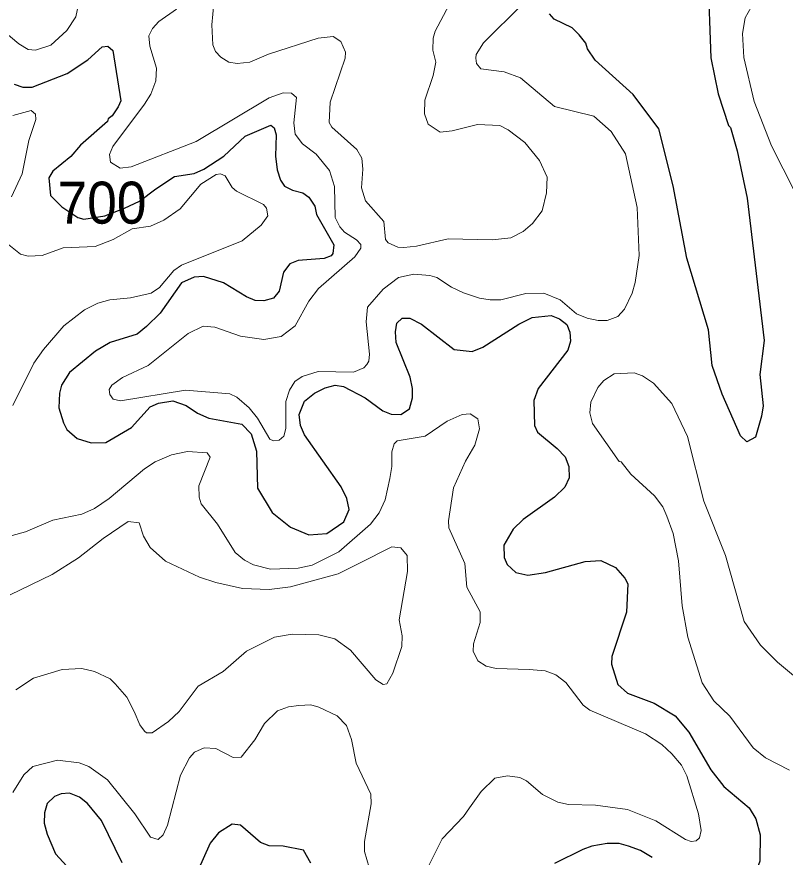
# Model space of a CAD drawing. Extents: x 294.2 to 320.3, y 7482.7 to 7510.7.
# Drawn here: x 307.613 to 309.078, y 7484.274 to 7485.877 of the extents above; entities that cross this region are included whole.
import ezdxf
from ezdxf.enums import TextEntityAlignment as Align

# ---------------------------------------------------------------- set-up
doc = ezdxf.new("R2010")
doc.units = 0
doc.header["$LTSCALE"] = 0.032
doc.layers.add('1', color=7, linetype='Continuous', lineweight=25)
doc.layers.add('2', color=7, linetype='Continuous', lineweight=13)
doc.layers.add('61', color=7, linetype='Continuous')

msp = doc.modelspace()

# ---------------------------------------------------------------- linework, layer by layer
at = {"layer": '1'}
for points in [[(308.9832, 7486.0825), (308.9632, 7486.0636), (308.9382, 7486.019), (308.9305, 7485.9565), (308.9358, 7485.7983), (308.9497, 7485.7295), (308.9699, 7485.6695)], [(308.9699, 7485.6695), (308.9737, 7485.6657), (308.9864, 7485.621), (309.005, 7485.531), (309.0376, 7485.259), (309.0297, 7485.1946), (309.0358, 7485.1349), (309.0325, 7485.115), (309.0209, 7485.0747), (309.0048, 7485.0661), (308.9926, 7485.0774), (308.9578, 7485.1569), (308.9386, 7485.2118), (308.9315, 7485.2798), (308.8901, 7485.4161), (308.864, 7485.554), (308.8367, 7485.6631), (308.7878, 7485.7287), (308.7157, 7485.7939), (308.7007, 7485.8159), (308.6974, 7485.8267), (308.6847, 7485.8423), (308.6719, 7485.8557), (308.6375, 7485.8724), (308.6281, 7485.8821)], [(307.6074, 7485.7481), (307.6241, 7485.7427), (307.6419, 7485.7427), (307.7084, 7485.7684), (307.7478, 7485.7948), (307.7756, 7485.8196), (307.7861, 7485.8207), (307.7956, 7485.8126), (307.8111, 7485.7162), (307.806, 7485.7047), (307.7945, 7485.688), (307.7868, 7485.6823), (307.7856, 7485.6772), (307.734, 7485.6318), (307.7159, 7485.6101), (307.6814, 7485.5821), (307.6737, 7485.5697), (307.677, 7485.5358), (307.6984, 7485.5142), (307.729, 7485.4938), (307.7401, 7485.4906), (307.7806, 7485.497), (307.8181, 7485.5117), (307.8464, 7485.5251), (307.8775, 7485.5483), (307.913, 7485.5719), (307.9507, 7485.5778), (307.969, 7485.5859), (308.0073, 7485.6111), (308.0478, 7485.6493), (308.0971, 7485.6697), (308.1032, 7485.6649), (308.1071, 7485.6514), (308.106, 7485.6111), (308.1088, 7485.5847), (308.1155, 7485.5653), (308.1233, 7485.5535), (308.1382, 7485.546), (308.1582, 7485.5411), (308.1693, 7485.5325), (308.181, 7485.5158), (308.1838, 7485.4997), (308.2171, 7485.4416), (308.2152, 7485.425), (308.212, 7485.4206), (308.1987, 7485.4154), (308.1489, 7485.4116), (308.1335, 7485.4052), (308.1214, 7485.3899), (308.1126, 7485.3533), (308.1021, 7485.3403), (308.0837, 7485.335), (308.0671, 7485.3356), (308.0505, 7485.3426), (308.0066, 7485.3695), (307.9683, 7485.3814), (307.951, 7485.3798), (307.9266, 7485.3691), (307.8862, 7485.3114)], [(307.6981, 7485.1738), (307.6942, 7485.1587), (307.6925, 7485.1307), (307.7014, 7485.1022), (307.708, 7485.0893), (307.728, 7485.0721), (307.7541, 7485.064), (307.7824, 7485.0646), (307.8312, 7485.0931), (307.8669, 7485.1326), (307.883, 7485.1396), (307.9102, 7485.1444), (307.9357, 7485.1353), (307.9573, 7485.1208), (307.979, 7485.1111), (308.0416, 7485.0998), (308.0594, 7485.0815), (308.0699, 7485.0482), (308.0716, 7484.9777), (308.0993, 7484.9309), (308.1343, 7484.903), (308.1693, 7484.8887), (308.2038, 7484.8913), (308.2363, 7484.9136), (308.2465, 7484.9366), (308.242, 7484.9577), (308.231, 7484.9802), (308.1611, 7485.0792), (308.1533, 7485.0969), (308.1511, 7485.1179), (308.1611, 7485.1437), (308.1805, 7485.1588), (308.2005, 7485.169), (308.2199, 7485.1738), (308.2354, 7485.1717), (308.277, 7485.1502), (308.3103, 7485.1249), (308.3264, 7485.119), (308.3452, 7485.1179), (308.3613, 7485.1287), (308.3674, 7485.1496), (308.3674, 7485.1679), (308.363, 7485.1894), (308.3358, 7485.2555), (308.3347, 7485.276), (308.3375, 7485.2926), (308.3475, 7485.3018), (308.3619, 7485.3018), (308.3841, 7485.2905), (308.4463, 7485.2421), (308.481, 7485.2385), (308.5015, 7485.2466), (308.5697, 7485.2902), (308.5952, 7485.3031), (308.6318, 7485.3068), (308.6473, 7485.3009), (308.6612, 7485.2901), (308.6673, 7485.2751), (308.6684, 7485.2579), (308.6634, 7485.2407), (308.6069, 7485.1675), (308.5986, 7485.1449), (308.5998, 7485.097), (308.6054, 7485.0841), (308.6431, 7485.0535), (308.6581, 7485.0373), (308.6653, 7485.019), (308.6659, 7484.997), (308.6576, 7484.9793), (308.6379, 7484.9602), (308.5779, 7484.9181), (308.5594, 7484.8995), (308.5415, 7484.8689), (308.5422, 7484.8453), (308.5478, 7484.8318), (308.5644, 7484.8167), (308.5872, 7484.8114), (308.6205, 7484.8167), (308.6965, 7484.8377), (308.726, 7484.8398), (308.7542, 7484.826), (308.7719, 7484.8061), (308.778, 7484.7948), (308.7753, 7484.741), (308.7471, 7484.6563), (308.7465, 7484.6416), (308.7586, 7484.6033), (308.7771, 7484.5867), (308.8282, 7484.5675), (308.8683, 7484.5435), (308.8938, 7484.5123), (308.936, 7484.4402), (308.961, 7484.4084), (309.0089, 7484.3676), (309.0219, 7484.3467)], [(307.8862, 7485.3114), (307.8601, 7485.2861), (307.8418, 7485.2716), (307.7908, 7485.2554), (307.7625, 7485.2392), (307.7131, 7485.198), (307.6981, 7485.1738)], [(307.8137, 7484.2631), (307.774, 7484.3434), (307.7474, 7484.3763), (307.7324, 7484.3881), (307.713, 7484.3956), (307.6975, 7484.3946), (307.6842, 7484.3892), (307.6703, 7484.3763), (307.6653, 7484.358), (307.6648, 7484.3387), (307.6703, 7484.3177), (307.6864, 7484.2801), (307.7147, 7484.2489)], [(309.0219, 7484.3467), (309.0298, 7484.3166), (309.0292, 7484.2662), (309.0108, 7484.2163), (309.0047, 7484.1669), (309.0075, 7484.1255), (309.0025, 7484.0868)], [(308.1734, 7484.2622), (308.159, 7484.2874), (308.1207, 7484.2944), (308.0941, 7484.2955), (308.0774, 7484.3019), (308.0391, 7484.3345), (308.0231, 7484.3364), (307.9972, 7484.3204), (307.9816, 7484.3005), (307.9572, 7484.2467)], [(308.8243, 7484.2732), (308.8021, 7484.2867), (308.7793, 7484.2948), (308.7615, 7484.2996), (308.7382, 7484.3001), (308.7088, 7484.2947), (308.6922, 7484.2882), (308.6379, 7484.2614)]]:
    msp.add_lwpolyline(points, dxfattribs=at)
at = {"layer": '2'}
for points in [[(308.4802, 7485.9818), (308.4106, 7485.849), (308.4068, 7485.8362), (308.4062, 7485.8132), (308.4119, 7485.7902), (308.4068, 7485.7647), (308.3908, 7485.7175), (308.3902, 7485.6919), (308.3972, 7485.6721), (308.4196, 7485.6568), (308.4426, 7485.6593), (308.4911, 7485.6714), (308.5338, 7485.6695), (308.5498, 7485.6612), (308.5811, 7485.637), (308.6092, 7485.6025), (308.6239, 7485.5706), (308.6226, 7485.5412), (308.6143, 7485.5068)], [(308.3749, 7485.439), (308.3506, 7485.4365), (308.3391, 7485.4372), (308.3206, 7485.4454), (308.3155, 7485.4518), (308.3123, 7485.4863), (308.2772, 7485.5259), (308.2701, 7485.5502), (308.2727, 7485.5859), (308.2708, 7485.607), (308.2612, 7485.6236), (308.2133, 7485.6664), (308.2082, 7485.6753), (308.2101, 7485.7136), (308.2389, 7485.7979), (308.2395, 7485.8094), (308.2306, 7485.8298), (308.2159, 7485.8394), (308.1872, 7485.8362), (308.0927, 7485.8055), (308.0569, 7485.7902), (308.0327, 7485.7876), (308.0167, 7485.7902), (308.0014, 7485.7998), (307.9912, 7485.8107), (307.9861, 7485.8234), (307.9848, 7485.8617), (307.9918, 7485.9435)], [(307.6164, 7485.8253), (307.6343, 7485.8145), (307.6483, 7485.8132), (307.6777, 7485.8228), (307.7083, 7485.8509), (307.7249, 7485.8764), (307.7332, 7485.916)], [(308.5154, 7485.3369), (308.5358, 7485.3369), (308.583, 7485.349), (308.6175, 7485.3496), (308.6488, 7485.3369), (308.6801, 7485.3101), (308.7005, 7485.3018), (308.7209, 7485.2973), (308.7381, 7485.2973), (308.7586, 7485.305), (308.7714, 7485.319), (308.786, 7485.3497), (308.7918, 7485.3701), (308.7995, 7485.4212), (308.7956, 7485.5131), (308.7733, 7485.6153), (308.7458, 7485.658), (308.7126, 7485.6874), (308.6379, 7485.7059), (308.5728, 7485.7602), (308.5422, 7485.7717), (308.4975, 7485.7774), (308.4892, 7485.7877), (308.4879, 7485.7979), (308.4885, 7485.8049), (308.5025, 7485.8273), (308.5766, 7485.9007)], [(309.0185, 7485.9051), (309.0018, 7485.8745), (308.9961, 7485.8451), (308.9987, 7485.7992), (309.0184, 7485.7149), (309.0516, 7485.6306), (309.1193, 7485.4978)], [(307.9171, 7485.8911), (307.8833, 7485.8675), (307.8711, 7485.8541), (307.8641, 7485.8406), (307.866, 7485.8209), (307.8788, 7485.7787), (307.8775, 7485.7545), (307.8679, 7485.7289), (307.8564, 7485.7098), (307.7958, 7485.6293), (307.7894, 7485.614), (307.7913, 7485.5993), (307.8098, 7485.5878), (307.8309, 7485.5904), (307.9548, 7485.6389), (308.094, 7485.7219), (308.1208, 7485.7315), (308.1367, 7485.7309), (308.1457, 7485.7226), (308.1406, 7485.6747), (308.1431, 7485.6529), (308.1572, 7485.6344), (308.1833, 7485.6146), (308.2089, 7485.5834), (308.2185, 7485.5527), (308.2197, 7485.494), (308.2287, 7485.4761), (308.2376, 7485.4658), (308.2606, 7485.4512), (308.2683, 7485.4422), (308.2683, 7485.4352), (308.2574, 7485.4186), (308.1878, 7485.3586), (308.1693, 7485.3344), (308.1437, 7485.2871), (308.1169, 7485.2666), (308.0837, 7485.2609), (308.0391, 7485.2673), (307.9905, 7485.2845), (307.9682, 7485.2865), (307.9394, 7485.2724), (307.8628, 7485.2117), (307.8143, 7485.1888), (307.7939, 7485.1741), (307.7887, 7485.1658), (307.79, 7485.1562), (307.7964, 7485.1473), (307.8105, 7485.1441), (307.9343, 7485.1645), (308.0186, 7485.1575), (308.032, 7485.1511), (308.0556, 7485.1307), (308.0716, 7485.1109), (308.0952, 7485.0713), (308.1022, 7485.0681), (308.1131, 7485.0694), (308.122, 7485.077), (308.1258, 7485.0917), (308.1258, 7485.1428), (308.1329, 7485.1645), (308.1425, 7485.1811), (308.1565, 7485.1907), (308.1872, 7485.2002), (308.2549, 7485.199), (308.2746, 7485.2073), (308.2798, 7485.2137), (308.2836, 7485.2201), (308.2849, 7485.2335), (308.2791, 7485.2948), (308.2816, 7485.3229), (308.311, 7485.3573), (308.3404, 7485.3797), (308.3698, 7485.3861)], [(307.4759, 7485.7283), (307.4861, 7485.7417), (307.5353, 7485.8349), (307.5481, 7485.8503), (307.5627, 7485.8598), (307.5761, 7485.8591), (307.6164, 7485.8253)], [(307.6049, 7485.6887), (307.64, 7485.6982), (307.6483, 7485.6913), (307.6489, 7485.681), (307.6355, 7485.6408), (307.6227, 7485.577), (307.6023, 7485.5336)], [(307.9634, 7485.5574), (307.9927, 7485.5758), (308.0007, 7485.5769), (308.0099, 7485.5736), (308.0231, 7485.5514), (308.0314, 7485.5444), (308.0831, 7485.5189), (308.0888, 7485.5119), (308.0914, 7485.4971), (308.0786, 7485.4793), (308.0422, 7485.4492), (307.9267, 7485.4027), (307.912, 7485.3931), (307.8845, 7485.3605), (307.8685, 7485.3496), (307.8296, 7485.3407), (307.79, 7485.3369), (307.7671, 7485.3305), (307.7415, 7485.3177), (307.7025, 7485.2871), (307.6636, 7485.2424), (307.6451, 7485.2162), (307.6048, 7485.1352)], [(307.762, 7485.4384), (307.7964, 7485.4518), (307.8325, 7485.472), (307.8675, 7485.4776), (307.8928, 7485.4887), (307.9238, 7485.5104), (307.9634, 7485.5574)], [(308.6143, 7485.5068), (308.5958, 7485.4825), (308.5779, 7485.4671), (308.5549, 7485.455), (308.5192, 7485.4512), (308.4349, 7485.4531), (308.3749, 7485.439)], [(307.594, 7485.4442), (307.6196, 7485.4237), (307.6343, 7485.4199), (307.6611, 7485.4212), (307.7013, 7485.4359), (307.762, 7485.4384)], [(308.3698, 7485.3861), (308.4004, 7485.3835), (308.4138, 7485.3797), (308.4413, 7485.3611), (308.4643, 7485.3503), (308.4949, 7485.3401), (308.5154, 7485.3369)], [(309.1091, 7484.6077), (309.0631, 7484.6454), (309.0306, 7484.678), (308.9993, 7484.7233), (308.9642, 7484.8491), (308.9227, 7484.9526), (308.8914, 7485.0764), (308.8614, 7485.139), (308.8269, 7485.1779), (308.8058, 7485.192), (308.7899, 7485.1977), (308.7516, 7485.1958), (308.7318, 7485.183), (308.7203, 7485.1696), (308.7069, 7485.1415), (308.705, 7485.1211), (308.7101, 7485.1007), (308.7612, 7485.0285), (308.765, 7485.0279), (308.7835, 7485.0042), (308.8288, 7484.9627), (308.8442, 7484.9423), (308.8524, 7484.9245), (308.8639, 7484.8913), (308.8741, 7484.8389), (308.8812, 7484.7534), (308.892, 7484.6933), (308.9195, 7484.6065), (308.9418, 7484.572), (308.9725, 7484.5427), (309.0165, 7484.4826), (309.0402, 7484.4635), (309.0862, 7484.4399)], [(307.6036, 7484.8874), (307.6292, 7484.8944), (307.6815, 7484.9168), (307.7364, 7484.9282), (307.7607, 7484.9391), (307.7888, 7484.9576), (307.8558, 7485.0145), (307.8762, 7485.0278), (307.9075, 7485.0413), (307.9382, 7485.0477), (307.9758, 7485.0451), (307.9815, 7485.0368), (307.9598, 7484.9819), (307.9605, 7484.9602), (307.9643, 7484.948), (307.9956, 7484.9091), (308.0288, 7484.8549), (308.0467, 7484.8401), (308.0639, 7484.8312), (308.0965, 7484.8229), (308.1489, 7484.8248), (308.1757, 7484.8306), (308.2268, 7484.8561), (308.2868, 7484.9091), (308.3033, 7484.9308), (308.3148, 7484.9551), (308.3238, 7484.996), (308.3276, 7485.019), (308.3276, 7485.047), (308.3321, 7485.0624), (308.3378, 7485.0681), (308.3915, 7485.0771), (308.433, 7485.1051), (308.4617, 7485.1179), (308.477, 7485.1192), (308.4917, 7485.1096), (308.4949, 7485.0905), (308.4859, 7485.0598), (308.4681, 7485.0292), (308.4451, 7484.9781), (308.4355, 7484.9155), (308.4362, 7484.9021), (308.4668, 7484.8338), (308.4706, 7484.7885), (308.4962, 7484.7419), (308.4962, 7484.7214), (308.4834, 7484.6806), (308.4828, 7484.6665), (308.4917, 7484.648), (308.5077, 7484.6378), (308.5268, 7484.6339), (308.5894, 7484.632), (308.6201, 7484.6294), (308.6405, 7484.6218), (308.6596, 7484.6071), (308.6928, 7484.5637), (308.705, 7484.5541), (308.8116, 7484.5088), (308.8423, 7484.4884), (308.8614, 7484.4711)], [(307.8666, 7484.8644), (307.8545, 7484.8862), (307.8462, 7484.9117), (307.8251, 7484.9142), (307.7773, 7484.8817), (307.73, 7484.8446), (307.6802, 7484.8127)], [(307.6106, 7484.5931), (307.6445, 7484.6154), (307.6994, 7484.6314), (307.7364, 7484.6333), (307.7607, 7484.6276), (307.7907, 7484.6141), (307.8002, 7484.6046), (307.8226, 7484.579), (307.8366, 7484.5516), (307.8469, 7484.5261), (307.8558, 7484.5139), (307.8596, 7484.5107), (307.8705, 7484.5107), (307.9018, 7484.5324), (307.9222, 7484.5516), (307.9586, 7484.6001), (308.0059, 7484.6282), (308.0505, 7484.6665), (308.1041, 7484.6933), (308.1374, 7484.6991), (308.1885, 7484.6978), (308.2191, 7484.6901), (308.2491, 7484.6684), (308.297, 7484.6122), (308.311, 7484.6033), (308.318, 7484.6046), (308.3296, 7484.6244), (308.3468, 7484.6755), (308.3474, 7484.6959), (308.3416, 7484.7265), (308.3576, 7484.8185), (308.357, 7484.8491), (308.3448, 7484.8638), (308.3276, 7484.8657), (308.2663, 7484.8344), (308.2255, 7484.814), (308.1348, 7484.7891), (308.094, 7484.784), (308.0429, 7484.7859), (307.9918, 7484.7974), (307.9612, 7484.8076), (307.896, 7484.8383), (307.8666, 7484.8644)], [(307.6802, 7484.8127), (307.5998, 7484.7744)], [(308.2887, 7484.2387), (308.2759, 7484.2847), (308.2759, 7484.3039), (308.288, 7484.3754), (308.2874, 7484.3939), (308.2599, 7484.4533), (308.251, 7484.498), (308.2414, 7484.5248), (308.2236, 7484.5433), (308.1885, 7484.5599), (308.1731, 7484.5643), (308.1501, 7484.563), (308.131, 7484.5605), (308.1099, 7484.5528), (308.085, 7484.5286), (308.0665, 7484.4973), (308.0403, 7484.4647), (308.025, 7484.4641), (307.9918, 7484.4813), (307.9701, 7484.4826), (307.9516, 7484.4743), (307.942, 7484.4635), (307.9248, 7484.4303), (307.8998, 7484.3345), (307.8916, 7484.3166), (307.882, 7484.3076), (307.8673, 7484.3121), (307.8379, 7484.3562), (307.7856, 7484.4213), (307.7498, 7484.4468), (307.7313, 7484.4539), (307.6904, 7484.459), (307.6432, 7484.4468), (307.6259, 7484.4309), (307.6049, 7484.3971)], [(308.8614, 7484.4711), (308.8799, 7484.4494), (308.8901, 7484.429), (308.9124, 7484.3562), (308.9175, 7484.3243), (308.9144, 7484.3108), (308.908, 7484.3051)], [(308.908, 7484.3051), (308.8984, 7484.3038), (308.8875, 7484.3076), (308.8314, 7484.3428), (308.7771, 7484.3645), (308.7158, 7484.3728), (308.6648, 7484.374), (308.6443, 7484.3786), (308.615, 7484.3932), (308.5843, 7484.4194), (308.5715, 7484.4258), (308.5486, 7484.429), (308.5242, 7484.4245), (308.4981, 7484.399), (308.4758, 7484.3677), (308.4642, 7484.3511), (308.424, 7484.309), (308.3787, 7484.2183)]]:
    msp.add_lwpolyline(points, dxfattribs=at)

# ---------------------------------------------------------------- texts
at = {"layer": '61', "width": 0.95}
msp.add_text('700', height=0.08, dxfattribs=at).set_placement((307.775, 7485.4822), align=Align.CENTER)

doc.saveas('drawing.dxf')
